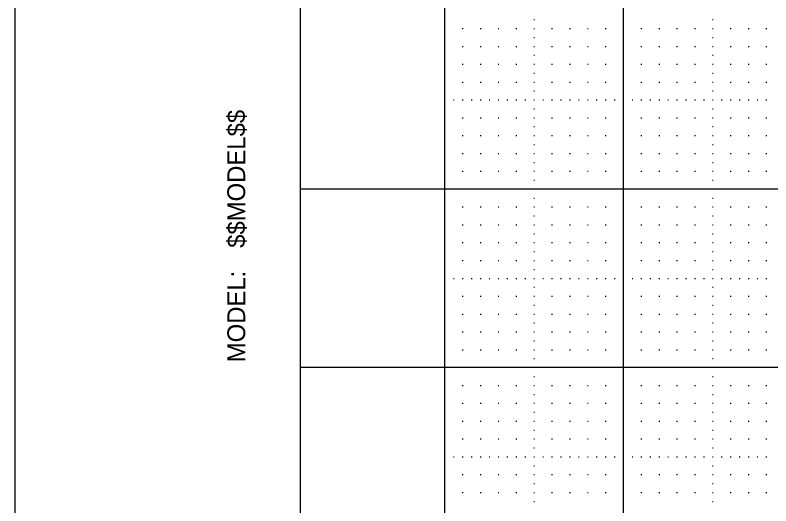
# Model space of a CAD drawing. Extents: x 0 to 34, y 0 to 22.
# Drawn here: x 0 to 4.231, y 5.497 to 8.247 of the extents above; entities that cross this region are included whole.
import ezdxf

# ---------------------------------------------------------------- set-up
doc = ezdxf.new("R2010")
doc.units = 0
for name, color, linetype in [('Level 1', 7, 'Continuous'), ('Level 4', 7, 'Continuous'), ('Level 5', 7, 'Continuous'), ('Level 63', 7, 'Continuous')]:
    doc.layers.add(name, color=color, linetype=linetype)

msp = doc.modelspace()

# ---------------------------------------------------------------- linework, layer by layer
at = {"layer": 'Level 1'}
msp.add_line((1.597, 0.726), (1.597, 21.272), dxfattribs=at)
at = {"layer": 'Level 4'}
for p, q in [((2.406, 1.272), (2.406, 21.272)), ((3.406, 1.272), (3.406, 21.272)), ((33.215, 7.272), (1.597, 7.272)), ((33.215, 6.272), (1.597, 6.272))]:
    msp.add_line(p, q, dxfattribs=at)
at = {"layer": 'Level 5'}
for p, q in [((2.9035, 8.222), (2.9085, 8.222)), ((3.9035, 8.222), (3.9085, 8.222)), ((2.5035, 8.172), (2.5085, 8.172)), ((2.6035, 8.172), (2.6085, 8.172)), ((2.7035, 8.172), (2.7085, 8.172)), ((2.8035, 8.172), (2.8085, 8.172)), ((2.9035, 8.172), (2.9085, 8.172)), ((3.0035, 8.172), (3.0085, 8.172)), ((3.1035, 8.172), (3.1085, 8.172)), ((3.2035, 8.172), (3.2085, 8.172)), ((3.3035, 8.172), (3.3085, 8.172)), ((3.5035, 8.172), (3.5085, 8.172)), ((3.6035, 8.172), (3.6085, 8.172)), ((3.7035, 8.172), (3.7085, 8.172)), ((3.8035, 8.172), (3.8085, 8.172)), ((3.9035, 8.172), (3.9085, 8.172)), ((4.0035, 8.172), (4.0085, 8.172)), ((4.1035, 8.172), (4.1085, 8.172)), ((4.2035, 8.172), (4.2085, 8.172)), ((2.9035, 8.122), (2.9085, 8.122)), ((3.9035, 8.122), (3.9085, 8.122)), ((2.5035, 8.072), (2.5085, 8.072)), ((2.6035, 8.072), (2.6085, 8.072)), ((2.7035, 8.072), (2.7085, 8.072)), ((2.8035, 8.072), (2.8085, 8.072)), ((2.9035, 8.072), (2.9085, 8.072)), ((3.0035, 8.072), (3.0085, 8.072)), ((3.1035, 8.072), (3.1085, 8.072)), ((3.2035, 8.072), (3.2085, 8.072)), ((3.3035, 8.072), (3.3085, 8.072)), ((3.5035, 8.072), (3.5085, 8.072)), ((3.6035, 8.072), (3.6085, 8.072)), ((3.7035, 8.072), (3.7085, 8.072)), ((3.8035, 8.072), (3.8085, 8.072)), ((3.9035, 8.072), (3.9085, 8.072)), ((4.0035, 8.072), (4.0085, 8.072)), ((4.1035, 8.072), (4.1085, 8.072)), ((4.2035, 8.072), (4.2085, 8.072)), ((2.9035, 8.022), (2.9085, 8.022)), ((3.9035, 8.022), (3.9085, 8.022)), ((2.5035, 7.972), (2.5085, 7.972)), ((2.6035, 7.972), (2.6085, 7.972)), ((2.7035, 7.972), (2.7085, 7.972)), ((2.8035, 7.972), (2.8085, 7.972)), ((2.9035, 7.972), (2.9085, 7.972)), ((3.0035, 7.972), (3.0085, 7.972)), ((3.1035, 7.972), (3.1085, 7.972)), ((3.2035, 7.972), (3.2085, 7.972)), ((3.3035, 7.972), (3.3085, 7.972)), ((3.5035, 7.972), (3.5085, 7.972)), ((3.6035, 7.972), (3.6085, 7.972)), ((3.7035, 7.972), (3.7085, 7.972)), ((3.8035, 7.972), (3.8085, 7.972)), ((3.9035, 7.972), (3.9085, 7.972)), ((4.0035, 7.972), (4.0085, 7.972)), ((4.1035, 7.972), (4.1085, 7.972)), ((4.2035, 7.972), (4.2085, 7.972)), ((2.9035, 7.922), (2.9085, 7.922)), ((3.9035, 7.922), (3.9085, 7.922)), ((2.5035, 7.872), (2.5085, 7.872)), ((2.6035, 7.872), (2.6085, 7.872)), ((2.7035, 7.872), (2.7085, 7.872)), ((2.8035, 7.872), (2.8085, 7.872)), ((2.9035, 7.872), (2.9085, 7.872)), ((3.0035, 7.872), (3.0085, 7.872)), ((3.1035, 7.872), (3.1085, 7.872)), ((3.2035, 7.872), (3.2085, 7.872)), ((3.3035, 7.872), (3.3085, 7.872)), ((3.5035, 7.872), (3.5085, 7.872)), ((3.6035, 7.872), (3.6085, 7.872)), ((3.7035, 7.872), (3.7085, 7.872)), ((3.8035, 7.872), (3.8085, 7.872)), ((3.9035, 7.872), (3.9085, 7.872)), ((4.0035, 7.872), (4.0085, 7.872)), ((4.1035, 7.872), (4.1085, 7.872)), ((4.2035, 7.872), (4.2085, 7.872)), ((2.9035, 7.822), (2.9085, 7.822)), ((3.9035, 7.822), (3.9085, 7.822)), ((2.4535, 7.772), (2.4585, 7.772)), ((2.5035, 7.772), (2.5085, 7.772)), ((2.5535, 7.772), (2.5585, 7.772)), ((2.6035, 7.772), (2.6085, 7.772)), ((2.6535, 7.772), (2.6585, 7.772)), ((2.7035, 7.772), (2.7085, 7.772)), ((2.7535, 7.772), (2.7585, 7.772)), ((2.8035, 7.772), (2.8085, 7.772)), ((2.8535, 7.772), (2.8585, 7.772)), ((2.9035, 7.772), (2.9085, 7.772)), ((2.9535, 7.772), (2.9585, 7.772)), ((3.0035, 7.772), (3.0085, 7.772)), ((3.0535, 7.772), (3.0585, 7.772)), ((3.1035, 7.772), (3.1085, 7.772)), ((3.1535, 7.772), (3.1585, 7.772)), ((3.2035, 7.772), (3.2085, 7.772)), ((3.2535, 7.772), (3.2585, 7.772)), ((3.3035, 7.772), (3.3085, 7.772)), ((3.3535, 7.772), (3.3585, 7.772)), ((3.4535, 7.772), (3.4585, 7.772)), ((3.5035, 7.772), (3.5085, 7.772)), ((3.5535, 7.772), (3.5585, 7.772)), ((3.6035, 7.772), (3.6085, 7.772)), ((3.6535, 7.772), (3.6585, 7.772)), ((3.7035, 7.772), (3.7085, 7.772)), ((3.7535, 7.772), (3.7585, 7.772)), ((3.8035, 7.772), (3.8085, 7.772)), ((3.8535, 7.772), (3.8585, 7.772)), ((3.9035, 7.772), (3.9085, 7.772)), ((3.9535, 7.772), (3.9585, 7.772)), ((4.0035, 7.772), (4.0085, 7.772)), ((4.0535, 7.772), (4.0585, 7.772)), ((4.1035, 7.772), (4.1085, 7.772)), ((4.1535, 7.772), (4.1585, 7.772)), ((4.2035, 7.772), (4.2085, 7.772)), ((2.9035, 7.722), (2.9085, 7.722)), ((3.9035, 7.722), (3.9085, 7.722)), ((2.5035, 7.672), (2.5085, 7.672)), ((2.6035, 7.672), (2.6085, 7.672)), ((2.7035, 7.672), (2.7085, 7.672)), ((2.8035, 7.672), (2.8085, 7.672)), ((2.9035, 7.672), (2.9085, 7.672)), ((3.0035, 7.672), (3.0085, 7.672)), ((3.1035, 7.672), (3.1085, 7.672)), ((3.2035, 7.672), (3.2085, 7.672)), ((3.3035, 7.672), (3.3085, 7.672)), ((3.5035, 7.672), (3.5085, 7.672)), ((3.6035, 7.672), (3.6085, 7.672)), ((3.7035, 7.672), (3.7085, 7.672)), ((3.8035, 7.672), (3.8085, 7.672)), ((3.9035, 7.672), (3.9085, 7.672)), ((4.0035, 7.672), (4.0085, 7.672)), ((4.1035, 7.672), (4.1085, 7.672)), ((4.2035, 7.672), (4.2085, 7.672)), ((2.9035, 7.622), (2.9085, 7.622)), ((3.9035, 7.622), (3.9085, 7.622)), ((2.5035, 7.572), (2.5085, 7.572)), ((2.6035, 7.572), (2.6085, 7.572)), ((2.7035, 7.572), (2.7085, 7.572)), ((2.8035, 7.572), (2.8085, 7.572)), ((2.9035, 7.572), (2.9085, 7.572)), ((3.0035, 7.572), (3.0085, 7.572)), ((3.1035, 7.572), (3.1085, 7.572)), ((3.2035, 7.572), (3.2085, 7.572)), ((3.3035, 7.572), (3.3085, 7.572)), ((3.5035, 7.572), (3.5085, 7.572)), ((3.6035, 7.572), (3.6085, 7.572)), ((3.7035, 7.572), (3.7085, 7.572)), ((3.8035, 7.572), (3.8085, 7.572)), ((3.9035, 7.572), (3.9085, 7.572)), ((4.0035, 7.572), (4.0085, 7.572)), ((4.1035, 7.572), (4.1085, 7.572)), ((4.2035, 7.572), (4.2085, 7.572)), ((2.9035, 7.522), (2.9085, 7.522)), ((3.9035, 7.522), (3.9085, 7.522)), ((2.5035, 7.472), (2.5085, 7.472)), ((2.6035, 7.472), (2.6085, 7.472)), ((2.7035, 7.472), (2.7085, 7.472)), ((2.8035, 7.472), (2.8085, 7.472)), ((2.9035, 7.472), (2.9085, 7.472)), ((3.0035, 7.472), (3.0085, 7.472)), ((3.1035, 7.472), (3.1085, 7.472)), ((3.2035, 7.472), (3.2085, 7.472)), ((3.3035, 7.472), (3.3085, 7.472)), ((3.5035, 7.472), (3.5085, 7.472)), ((3.6035, 7.472), (3.6085, 7.472)), ((3.7035, 7.472), (3.7085, 7.472)), ((3.8035, 7.472), (3.8085, 7.472)), ((3.9035, 7.472), (3.9085, 7.472)), ((4.0035, 7.472), (4.0085, 7.472)), ((4.1035, 7.472), (4.1085, 7.472)), ((4.2035, 7.472), (4.2085, 7.472)), ((2.9035, 7.422), (2.9085, 7.422)), ((3.9035, 7.422), (3.9085, 7.422)), ((2.5035, 7.372), (2.5085, 7.372)), ((2.6035, 7.372), (2.6085, 7.372)), ((2.7035, 7.372), (2.7085, 7.372)), ((2.8035, 7.372), (2.8085, 7.372)), ((2.9035, 7.372), (2.9085, 7.372)), ((3.0035, 7.372), (3.0085, 7.372)), ((3.1035, 7.372), (3.1085, 7.372)), ((3.2035, 7.372), (3.2085, 7.372)), ((3.3035, 7.372), (3.3085, 7.372)), ((3.5035, 7.372), (3.5085, 7.372)), ((3.6035, 7.372), (3.6085, 7.372)), ((3.7035, 7.372), (3.7085, 7.372)), ((3.8035, 7.372), (3.8085, 7.372)), ((3.9035, 7.372), (3.9085, 7.372)), ((4.0035, 7.372), (4.0085, 7.372)), ((4.1035, 7.372), (4.1085, 7.372)), ((4.2035, 7.372), (4.2085, 7.372)), ((2.9035, 7.322), (2.9085, 7.322)), ((3.9035, 7.322), (3.9085, 7.322)), ((2.9035, 7.222), (2.9085, 7.222)), ((3.9035, 7.222), (3.9085, 7.222)), ((2.5035, 7.172), (2.5085, 7.172)), ((2.6035, 7.172), (2.6085, 7.172)), ((2.7035, 7.172), (2.7085, 7.172)), ((2.8035, 7.172), (2.8085, 7.172)), ((2.9035, 7.172), (2.9085, 7.172)), ((3.0035, 7.172), (3.0085, 7.172)), ((3.1035, 7.172), (3.1085, 7.172)), ((3.2035, 7.172), (3.2085, 7.172)), ((3.3035, 7.172), (3.3085, 7.172)), ((3.5035, 7.172), (3.5085, 7.172)), ((3.6035, 7.172), (3.6085, 7.172)), ((3.7035, 7.172), (3.7085, 7.172)), ((3.8035, 7.172), (3.8085, 7.172)), ((3.9035, 7.172), (3.9085, 7.172)), ((4.0035, 7.172), (4.0085, 7.172)), ((4.1035, 7.172), (4.1085, 7.172)), ((4.2035, 7.172), (4.2085, 7.172)), ((2.9035, 7.122), (2.9085, 7.122)), ((3.9035, 7.122), (3.9085, 7.122)), ((2.5035, 7.072), (2.5085, 7.072)), ((2.6035, 7.072), (2.6085, 7.072)), ((2.7035, 7.072), (2.7085, 7.072)), ((2.8035, 7.072), (2.8085, 7.072)), ((2.9035, 7.072), (2.9085, 7.072)), ((3.0035, 7.072), (3.0085, 7.072)), ((3.1035, 7.072), (3.1085, 7.072)), ((3.2035, 7.072), (3.2085, 7.072)), ((3.3035, 7.072), (3.3085, 7.072)), ((3.5035, 7.072), (3.5085, 7.072)), ((3.6035, 7.072), (3.6085, 7.072)), ((3.7035, 7.072), (3.7085, 7.072)), ((3.8035, 7.072), (3.8085, 7.072)), ((3.9035, 7.072), (3.9085, 7.072)), ((4.0035, 7.072), (4.0085, 7.072)), ((4.1035, 7.072), (4.1085, 7.072)), ((4.2035, 7.072), (4.2085, 7.072)), ((2.9035, 7.022), (2.9085, 7.022)), ((3.9035, 7.022), (3.9085, 7.022)), ((2.5035, 6.972), (2.5085, 6.972)), ((2.6035, 6.972), (2.6085, 6.972)), ((2.7035, 6.972), (2.7085, 6.972)), ((2.8035, 6.972), (2.8085, 6.972)), ((2.9035, 6.972), (2.9085, 6.972)), ((3.0035, 6.972), (3.0085, 6.972)), ((3.1035, 6.972), (3.1085, 6.972)), ((3.2035, 6.972), (3.2085, 6.972)), ((3.3035, 6.972), (3.3085, 6.972)), ((3.5035, 6.972), (3.5085, 6.972)), ((3.6035, 6.972), (3.6085, 6.972)), ((3.7035, 6.972), (3.7085, 6.972)), ((3.8035, 6.972), (3.8085, 6.972)), ((3.9035, 6.972), (3.9085, 6.972)), ((4.0035, 6.972), (4.0085, 6.972)), ((4.1035, 6.972), (4.1085, 6.972)), ((4.2035, 6.972), (4.2085, 6.972)), ((2.9035, 6.922), (2.9085, 6.922)), ((3.9035, 6.922), (3.9085, 6.922)), ((2.5035, 6.872), (2.5085, 6.872)), ((2.6035, 6.872), (2.6085, 6.872)), ((2.7035, 6.872), (2.7085, 6.872)), ((2.8035, 6.872), (2.8085, 6.872)), ((2.9035, 6.872), (2.9085, 6.872)), ((3.0035, 6.872), (3.0085, 6.872)), ((3.1035, 6.872), (3.1085, 6.872)), ((3.2035, 6.872), (3.2085, 6.872)), ((3.3035, 6.872), (3.3085, 6.872)), ((3.5035, 6.872), (3.5085, 6.872)), ((3.6035, 6.872), (3.6085, 6.872)), ((3.7035, 6.872), (3.7085, 6.872)), ((3.8035, 6.872), (3.8085, 6.872)), ((3.9035, 6.872), (3.9085, 6.872)), ((4.0035, 6.872), (4.0085, 6.872)), ((4.1035, 6.872), (4.1085, 6.872)), ((4.2035, 6.872), (4.2085, 6.872)), ((2.9035, 6.822), (2.9085, 6.822)), ((3.9035, 6.822), (3.9085, 6.822)), ((2.4535, 6.772), (2.4585, 6.772)), ((2.5035, 6.772), (2.5085, 6.772)), ((2.5535, 6.772), (2.5585, 6.772)), ((2.6035, 6.772), (2.6085, 6.772)), ((2.6535, 6.772), (2.6585, 6.772)), ((2.7035, 6.772), (2.7085, 6.772)), ((2.7535, 6.772), (2.7585, 6.772)), ((2.8035, 6.772), (2.8085, 6.772)), ((2.8535, 6.772), (2.8585, 6.772)), ((2.9035, 6.772), (2.9085, 6.772)), ((2.9535, 6.772), (2.9585, 6.772)), ((3.0035, 6.772), (3.0085, 6.772)), ((3.0535, 6.772), (3.0585, 6.772)), ((3.1035, 6.772), (3.1085, 6.772)), ((3.1535, 6.772), (3.1585, 6.772)), ((3.2035, 6.772), (3.2085, 6.772)), ((3.2535, 6.772), (3.2585, 6.772)), ((3.3035, 6.772), (3.3085, 6.772)), ((3.3535, 6.772), (3.3585, 6.772)), ((3.4535, 6.772), (3.4585, 6.772)), ((3.5035, 6.772), (3.5085, 6.772)), ((3.5535, 6.772), (3.5585, 6.772)), ((3.6035, 6.772), (3.6085, 6.772)), ((3.6535, 6.772), (3.6585, 6.772)), ((3.7035, 6.772), (3.7085, 6.772)), ((3.7535, 6.772), (3.7585, 6.772)), ((3.8035, 6.772), (3.8085, 6.772)), ((3.8535, 6.772), (3.8585, 6.772)), ((3.9035, 6.772), (3.9085, 6.772)), ((3.9535, 6.772), (3.9585, 6.772)), ((4.0035, 6.772), (4.0085, 6.772)), ((4.0535, 6.772), (4.0585, 6.772)), ((4.1035, 6.772), (4.1085, 6.772)), ((4.1535, 6.772), (4.1585, 6.772)), ((4.2035, 6.772), (4.2085, 6.772)), ((2.9035, 6.722), (2.9085, 6.722)), ((3.9035, 6.722), (3.9085, 6.722)), ((2.5035, 6.672), (2.5085, 6.672)), ((2.6035, 6.672), (2.6085, 6.672)), ((2.7035, 6.672), (2.7085, 6.672)), ((2.8035, 6.672), (2.8085, 6.672)), ((2.9035, 6.672), (2.9085, 6.672)), ((3.0035, 6.672), (3.0085, 6.672)), ((3.1035, 6.672), (3.1085, 6.672)), ((3.2035, 6.672), (3.2085, 6.672)), ((3.3035, 6.672), (3.3085, 6.672)), ((3.5035, 6.672), (3.5085, 6.672)), ((3.6035, 6.672), (3.6085, 6.672)), ((3.7035, 6.672), (3.7085, 6.672)), ((3.8035, 6.672), (3.8085, 6.672)), ((3.9035, 6.672), (3.9085, 6.672)), ((4.0035, 6.672), (4.0085, 6.672)), ((4.1035, 6.672), (4.1085, 6.672)), ((4.2035, 6.672), (4.2085, 6.672)), ((2.9035, 6.622), (2.9085, 6.622)), ((3.9035, 6.622), (3.9085, 6.622)), ((2.5035, 6.572), (2.5085, 6.572)), ((2.6035, 6.572), (2.6085, 6.572)), ((2.7035, 6.572), (2.7085, 6.572)), ((2.8035, 6.572), (2.8085, 6.572)), ((2.9035, 6.572), (2.9085, 6.572)), ((3.0035, 6.572), (3.0085, 6.572)), ((3.1035, 6.572), (3.1085, 6.572)), ((3.2035, 6.572), (3.2085, 6.572)), ((3.3035, 6.572), (3.3085, 6.572)), ((3.5035, 6.572), (3.5085, 6.572)), ((3.6035, 6.572), (3.6085, 6.572)), ((3.7035, 6.572), (3.7085, 6.572)), ((3.8035, 6.572), (3.8085, 6.572)), ((3.9035, 6.572), (3.9085, 6.572)), ((4.0035, 6.572), (4.0085, 6.572)), ((4.1035, 6.572), (4.1085, 6.572)), ((4.2035, 6.572), (4.2085, 6.572)), ((2.9035, 6.522), (2.9085, 6.522)), ((3.9035, 6.522), (3.9085, 6.522)), ((2.5035, 6.472), (2.5085, 6.472)), ((2.6035, 6.472), (2.6085, 6.472)), ((2.7035, 6.472), (2.7085, 6.472)), ((2.8035, 6.472), (2.8085, 6.472)), ((2.9035, 6.472), (2.9085, 6.472)), ((3.0035, 6.472), (3.0085, 6.472)), ((3.1035, 6.472), (3.1085, 6.472)), ((3.2035, 6.472), (3.2085, 6.472)), ((3.3035, 6.472), (3.3085, 6.472)), ((3.5035, 6.472), (3.5085, 6.472)), ((3.6035, 6.472), (3.6085, 6.472)), ((3.7035, 6.472), (3.7085, 6.472)), ((3.8035, 6.472), (3.8085, 6.472)), ((3.9035, 6.472), (3.9085, 6.472)), ((4.0035, 6.472), (4.0085, 6.472)), ((4.1035, 6.472), (4.1085, 6.472)), ((4.2035, 6.472), (4.2085, 6.472)), ((2.9035, 6.422), (2.9085, 6.422)), ((3.9035, 6.422), (3.9085, 6.422)), ((2.5035, 6.372), (2.5085, 6.372)), ((2.6035, 6.372), (2.6085, 6.372)), ((2.7035, 6.372), (2.7085, 6.372)), ((2.8035, 6.372), (2.8085, 6.372)), ((2.9035, 6.372), (2.9085, 6.372)), ((3.0035, 6.372), (3.0085, 6.372)), ((3.1035, 6.372), (3.1085, 6.372)), ((3.2035, 6.372), (3.2085, 6.372)), ((3.3035, 6.372), (3.3085, 6.372)), ((3.5035, 6.372), (3.5085, 6.372)), ((3.6035, 6.372), (3.6085, 6.372)), ((3.7035, 6.372), (3.7085, 6.372)), ((3.8035, 6.372), (3.8085, 6.372)), ((3.9035, 6.372), (3.9085, 6.372)), ((4.0035, 6.372), (4.0085, 6.372)), ((4.1035, 6.372), (4.1085, 6.372)), ((4.2035, 6.372), (4.2085, 6.372)), ((2.9035, 6.322), (2.9085, 6.322)), ((3.9035, 6.322), (3.9085, 6.322)), ((2.9035, 6.222), (2.9085, 6.222)), ((3.9035, 6.222), (3.9085, 6.222)), ((2.5035, 6.172), (2.5085, 6.172)), ((2.6035, 6.172), (2.6085, 6.172)), ((2.7035, 6.172), (2.7085, 6.172)), ((2.8035, 6.172), (2.8085, 6.172)), ((2.9035, 6.172), (2.9085, 6.172)), ((3.0035, 6.172), (3.0085, 6.172)), ((3.1035, 6.172), (3.1085, 6.172)), ((3.2035, 6.172), (3.2085, 6.172)), ((3.3035, 6.172), (3.3085, 6.172)), ((3.5035, 6.172), (3.5085, 6.172)), ((3.6035, 6.172), (3.6085, 6.172)), ((3.7035, 6.172), (3.7085, 6.172)), ((3.8035, 6.172), (3.8085, 6.172)), ((3.9035, 6.172), (3.9085, 6.172)), ((4.0035, 6.172), (4.0085, 6.172)), ((4.1035, 6.172), (4.1085, 6.172)), ((4.2035, 6.172), (4.2085, 6.172)), ((2.9035, 6.122), (2.9085, 6.122)), ((3.9035, 6.122), (3.9085, 6.122)), ((2.5035, 6.072), (2.5085, 6.072)), ((2.6035, 6.072), (2.6085, 6.072)), ((2.7035, 6.072), (2.7085, 6.072)), ((2.8035, 6.072), (2.8085, 6.072)), ((2.9035, 6.072), (2.9085, 6.072)), ((3.0035, 6.072), (3.0085, 6.072)), ((3.1035, 6.072), (3.1085, 6.072)), ((3.2035, 6.072), (3.2085, 6.072)), ((3.3035, 6.072), (3.3085, 6.072)), ((3.5035, 6.072), (3.5085, 6.072)), ((3.6035, 6.072), (3.6085, 6.072)), ((3.7035, 6.072), (3.7085, 6.072)), ((3.8035, 6.072), (3.8085, 6.072)), ((3.9035, 6.072), (3.9085, 6.072)), ((4.0035, 6.072), (4.0085, 6.072)), ((4.1035, 6.072), (4.1085, 6.072)), ((4.2035, 6.072), (4.2085, 6.072)), ((2.9035, 6.022), (2.9085, 6.022)), ((3.9035, 6.022), (3.9085, 6.022)), ((2.5035, 5.972), (2.5085, 5.972)), ((2.6035, 5.972), (2.6085, 5.972)), ((2.7035, 5.972), (2.7085, 5.972)), ((2.8035, 5.972), (2.8085, 5.972)), ((2.9035, 5.972), (2.9085, 5.972)), ((3.0035, 5.972), (3.0085, 5.972)), ((3.1035, 5.972), (3.1085, 5.972)), ((3.2035, 5.972), (3.2085, 5.972)), ((3.3035, 5.972), (3.3085, 5.972)), ((3.5035, 5.972), (3.5085, 5.972)), ((3.6035, 5.972), (3.6085, 5.972)), ((3.7035, 5.972), (3.7085, 5.972)), ((3.8035, 5.972), (3.8085, 5.972)), ((3.9035, 5.972), (3.9085, 5.972)), ((4.0035, 5.972), (4.0085, 5.972)), ((4.1035, 5.972), (4.1085, 5.972)), ((4.2035, 5.972), (4.2085, 5.972)), ((2.9035, 5.922), (2.9085, 5.922)), ((3.9035, 5.922), (3.9085, 5.922)), ((2.5035, 5.872), (2.5085, 5.872)), ((2.6035, 5.872), (2.6085, 5.872)), ((2.7035, 5.872), (2.7085, 5.872)), ((2.8035, 5.872), (2.8085, 5.872)), ((2.9035, 5.872), (2.9085, 5.872)), ((3.0035, 5.872), (3.0085, 5.872)), ((3.1035, 5.872), (3.1085, 5.872)), ((3.2035, 5.872), (3.2085, 5.872)), ((3.3035, 5.872), (3.3085, 5.872)), ((3.5035, 5.872), (3.5085, 5.872)), ((3.6035, 5.872), (3.6085, 5.872)), ((3.7035, 5.872), (3.7085, 5.872)), ((3.8035, 5.872), (3.8085, 5.872)), ((3.9035, 5.872), (3.9085, 5.872)), ((4.0035, 5.872), (4.0085, 5.872)), ((4.1035, 5.872), (4.1085, 5.872)), ((4.2035, 5.872), (4.2085, 5.872)), ((2.9035, 5.822), (2.9085, 5.822)), ((3.9035, 5.822), (3.9085, 5.822)), ((2.4535, 5.772), (2.4585, 5.772)), ((2.5035, 5.772), (2.5085, 5.772)), ((2.5535, 5.772), (2.5585, 5.772)), ((2.6035, 5.772), (2.6085, 5.772)), ((2.6535, 5.772), (2.6585, 5.772)), ((2.7035, 5.772), (2.7085, 5.772)), ((2.7535, 5.772), (2.7585, 5.772)), ((2.8035, 5.772), (2.8085, 5.772)), ((2.8535, 5.772), (2.8585, 5.772)), ((2.9035, 5.772), (2.9085, 5.772)), ((2.9535, 5.772), (2.9585, 5.772)), ((3.0035, 5.772), (3.0085, 5.772)), ((3.0535, 5.772), (3.0585, 5.772)), ((3.1035, 5.772), (3.1085, 5.772)), ((3.1535, 5.772), (3.1585, 5.772)), ((3.2035, 5.772), (3.2085, 5.772)), ((3.2535, 5.772), (3.2585, 5.772)), ((3.3035, 5.772), (3.3085, 5.772)), ((3.3535, 5.772), (3.3585, 5.772)), ((3.4535, 5.772), (3.4585, 5.772)), ((3.5035, 5.772), (3.5085, 5.772)), ((3.5535, 5.772), (3.5585, 5.772)), ((3.6035, 5.772), (3.6085, 5.772)), ((3.6535, 5.772), (3.6585, 5.772)), ((3.7035, 5.772), (3.7085, 5.772)), ((3.7535, 5.772), (3.7585, 5.772)), ((3.8035, 5.772), (3.8085, 5.772)), ((3.8535, 5.772), (3.8585, 5.772)), ((3.9035, 5.772), (3.9085, 5.772)), ((3.9535, 5.772), (3.9585, 5.772)), ((4.0035, 5.772), (4.0085, 5.772)), ((4.0535, 5.772), (4.0585, 5.772)), ((4.1035, 5.772), (4.1085, 5.772)), ((4.1535, 5.772), (4.1585, 5.772)), ((4.2035, 5.772), (4.2085, 5.772)), ((2.9035, 5.722), (2.9085, 5.722)), ((3.9035, 5.722), (3.9085, 5.722)), ((2.5035, 5.672), (2.5085, 5.672)), ((2.6035, 5.672), (2.6085, 5.672)), ((2.7035, 5.672), (2.7085, 5.672)), ((2.8035, 5.672), (2.8085, 5.672)), ((2.9035, 5.672), (2.9085, 5.672)), ((3.0035, 5.672), (3.0085, 5.672)), ((3.1035, 5.672), (3.1085, 5.672)), ((3.2035, 5.672), (3.2085, 5.672)), ((3.3035, 5.672), (3.3085, 5.672)), ((3.5035, 5.672), (3.5085, 5.672)), ((3.6035, 5.672), (3.6085, 5.672)), ((3.7035, 5.672), (3.7085, 5.672)), ((3.8035, 5.672), (3.8085, 5.672)), ((3.9035, 5.672), (3.9085, 5.672)), ((4.0035, 5.672), (4.0085, 5.672)), ((4.1035, 5.672), (4.1085, 5.672)), ((4.2035, 5.672), (4.2085, 5.672)), ((2.9035, 5.622), (2.9085, 5.622)), ((3.9035, 5.622), (3.9085, 5.622)), ((2.5035, 5.572), (2.5085, 5.572)), ((2.6035, 5.572), (2.6085, 5.572)), ((2.7035, 5.572), (2.7085, 5.572)), ((2.8035, 5.572), (2.8085, 5.572)), ((2.9035, 5.572), (2.9085, 5.572)), ((3.0035, 5.572), (3.0085, 5.572)), ((3.1035, 5.572), (3.1085, 5.572)), ((3.2035, 5.572), (3.2085, 5.572)), ((3.3035, 5.572), (3.3085, 5.572)), ((3.5035, 5.572), (3.5085, 5.572)), ((3.6035, 5.572), (3.6085, 5.572)), ((3.7035, 5.572), (3.7085, 5.572)), ((3.8035, 5.572), (3.8085, 5.572)), ((3.9035, 5.572), (3.9085, 5.572)), ((4.0035, 5.572), (4.0085, 5.572)), ((4.1035, 5.572), (4.1085, 5.572)), ((4.2035, 5.572), (4.2085, 5.572)), ((2.9035, 5.522), (2.9085, 5.522)), ((3.9035, 5.522), (3.9085, 5.522))]:
    msp.add_line(p, q, dxfattribs=at)
at = {"layer": 'Level 63'}
msp.add_lwpolyline([(0, 22), (34, 22), (34, 0), (0, 0)], close=True, dxfattribs=at)

# ---------------------------------------------------------------- texts
at = {"layer": 'Level 1'}
for s, p in [('$$MODEL$$', (1.288, 6.943)), ('MODEL:', (1.288, 6.302))]:
    msp.add_text(s, height=0.1, rotation=90, dxfattribs=at).set_placement(p)

doc.saveas('drawing.dxf')
